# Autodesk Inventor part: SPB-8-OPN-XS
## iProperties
Author: ARennick
Shininess: 86.0
PropertySet Name: _Private Model Information
Created: 2001-03
Part Number: SPB-8-OPN-XS
Document SubType Name: Modeling
Designer: ARennick
Material: Aluminum-6061
Description: SPB-8-OPN-XS Pillow Block
Vendor: Thomson Ind.
Control State: 0
Master: False
Checked Out: False
PropertySet Name: Design Tracking Control
Density: 2.71
Volumn: 33.25423334274148
Area: 91.00053368228802
PropertySet Name: Model Information
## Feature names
1. Extrusion1
2. Extrusion2
3. Extrusion3
4. Hole1
